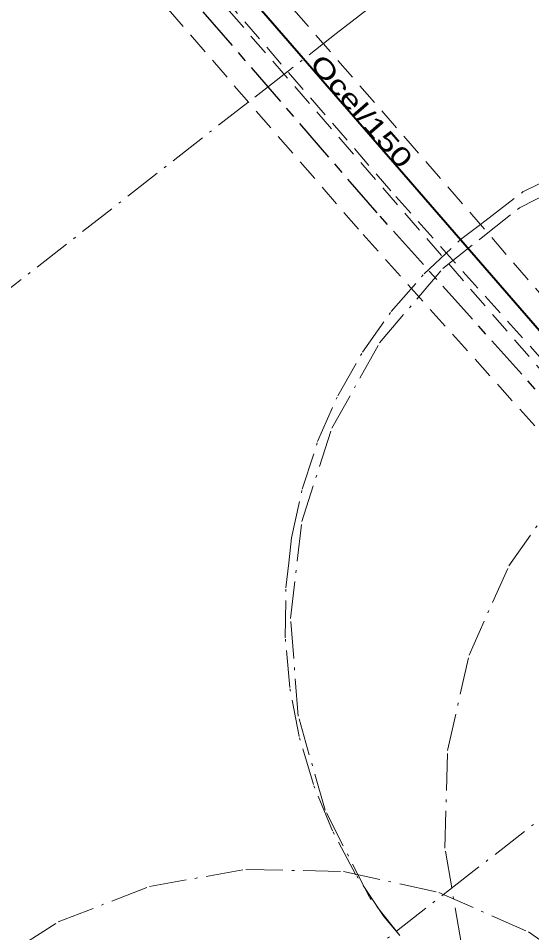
# Model space of a CAD drawing. Extents: x -588392 to -586332, y -1208963 to -1206334.
# Drawn here: x -587924.07 to -587903.38, y -1206828.1 to -1206791.27 of the extents above; entities that cross this region are included whole.
import ezdxf

# ---------------------------------------------------------------- set-up
doc = ezdxf.new("R2010")
doc.units = 0
doc.header["$LTSCALE"] = 0.3
for name, pattern in [('DOT_DASHED', [7.7, 5, -1.2, 0.3, -1.2]), ('LONG_DASH_SHORT_DASH', [9.9, 6, -1.2, 1.5, -1.2]), ('MEDIUM_DASHED', [4.5, 3, -1.5])]:
    doc.linetypes.add(name, pattern=pattern)
for name, color, linetype, lineweight in [('1', 7, 'MEDIUM_DASHED', 13), ('24', 7, 'Continuous', 25), ('51', 7, 'MEDIUM_DASHED', 13), ('55', 7, 'LONG_DASH_SHORT_DASH', 25), ('7', 7, 'MEDIUM_DASHED', 13)]:
    doc.layers.add(name, color=color, linetype=linetype, lineweight=lineweight)
doc.layers.add('30', color=7, linetype='Continuous')

msp = doc.modelspace()

# ---------------------------------------------------------------- linework, layer by layer
at = {"layer": '1'}
msp.add_lwpolyline([(-587926.025, -1206775.891), (-587925.751, -1206776.201), (-587925.351, -1206776.654), (-587897.549, -1206808.683), (-587897.277, -1206808.996), (-587897.335, -1206809.823), (-587897.648, -1206810.094), (-587897.961, -1206810.366), (-587898.788, -1206810.308), (-587899.059, -1206809.995), (-587926.857, -1206777.972), (-587927.251, -1206777.525), (-587927.525, -1206777.214), (-587927.473, -1206776.387), (-587927.163, -1206776.113), (-587926.852, -1206775.839)], close=True, dxfattribs=at)
at = {"layer": '1', "linetype": 'DOT_DASHED'}
for points in [[(-587925.141, -1206802.72), (-587914.541, -1206794.443), (-587914.182, -1206794.163), (-587911.256, -1206791.883), (-587910.616, -1206791.384), (-587902.174, -1206784.801)], [(-587908.7, -1206828.22), (-587909.343, -1206827.445), (-587910.465, -1206825.773), (-587911.415, -1206823.996), (-587912.181, -1206822.134), (-587912.755, -1206820.203), (-587913.133, -1206818.225), (-587913.311, -1206816.219), (-587913.286, -1206814.206), (-587913.172, -1206813.205), (-587913.058, -1206812.204), (-587912.632, -1206810.236), (-587912.009, -1206808.321), (-587911.197, -1206806.477), (-587910.204, -1206804.725), (-587909.041, -1206803.081), (-587907.718, -1206801.563), (-587906.249, -1206800.185), (-587905.449, -1206799.573), (-587905.279, -1206799.443), (-587903.714, -1206798.246), (-587900.178, -1206796.51)], [(-587908.696, -1206828.217), (-587909.918, -1206826.672), (-587911.712, -1206823.165), (-587912.788, -1206819.375), (-587913.104, -1206815.448), (-587912.647, -1206811.535), (-587911.435, -1206807.786), (-587909.516, -1206804.346), (-587906.962, -1206801.346), (-587905.417, -1206800.124), (-587903.872, -1206798.902), (-587900.365, -1206797.108)], [(-587906.215, -1206828.582), (-587906.881, -1206824.698), (-587906.775, -1206820.76), (-587905.904, -1206816.918), (-587904.3, -1206813.319), (-587902.025, -1206810.103), (-587900.595, -1206808.748), (-587899.165, -1206807.393), (-587895.832, -1206805.292), (-587892.154, -1206803.883), (-587888.27, -1206803.217), (-587884.332, -1206803.323), (-587880.49, -1206804.194), (-587876.891, -1206805.798), (-587873.675, -1206808.073), (-587872.32, -1206809.503), (-587872.156, -1206809.676), (-587870.801, -1206811.106), (-587868.7, -1206814.439), (-587867.291, -1206818.117), (-587866.625, -1206822.001), (-587866.731, -1206825.939), (-587867.602, -1206829.781)], [(-587980.539, -1206914.219), (-587943.819, -1206854.247), (-587929.75, -1206834.129), (-587928.621, -1206832.515), (-587925.777, -1206829.788), (-587922.456, -1206827.669), (-587918.785, -1206826.239), (-587914.906, -1206825.553), (-587910.967, -1206825.636), (-587907.12, -1206826.487), (-587903.513, -1206828.071), (-587901.899, -1206829.2), (-587900.285, -1206830.329), (-587897.558, -1206833.173), (-587895.439, -1206836.494), (-587894.009, -1206840.165), (-587893.323, -1206844.044), (-587893.406, -1206847.983), (-587894.257, -1206851.83), (-587895.841, -1206855.437), (-587896.97, -1206857.051), (-587910.341, -1206876.173), (-587946.581, -1206935.361)]]:
    msp.add_lwpolyline(points, dxfattribs=at)
at = {"layer": '24', "lineweight": 40}
msp.add_lwpolyline([(-587926.501, -1206776.863), (-587926.104, -1206777.313), (-587898.304, -1206809.339)], dxfattribs=at)
at = {"layer": '51', "linetype": 'DOT_DASHED'}
msp.add_lwpolyline([(-587912.489, -1206830.893), (-587906.69, -1206826.375), (-587896.084, -1206818.093), (-587895.738, -1206817.823), (-587892.817, -1206815.548), (-587892.171, -1206815.044), (-587883.726, -1206808.458), (-587872.95, -1206800.055), (-587829.182, -1206765.921)], dxfattribs=at)
at = {"layer": '55'}
msp.add_lwpolyline([(-587894.342, -1206810.552), (-587894.539, -1206810.692), (-587896.46, -1206812.27), (-587897.208, -1206812.884), (-587899.82, -1206810.03), (-587909.61, -1206799.11), (-587921.01, -1206785.93), (-587925.2, -1206780.79)], dxfattribs=at)
at = {"layer": '7'}
msp.add_lwpolyline([(-587920.244, -1206785.287), (-587908.859, -1206798.449), (-587899.079, -1206809.359), (-587897.11, -1206811.51), (-587897.095, -1206811.497), (-587895.147, -1206809.897), (-587894.921, -1206809.737), (-587894.583, -1206809.497), (-587893.767, -1206809.635), (-587893.527, -1206809.973), (-587893.287, -1206810.311), (-587893.425, -1206811.127), (-587893.763, -1206811.367), (-587893.931, -1206811.487), (-587895.825, -1206813.043), (-587896.574, -1206813.657), (-587896.882, -1206813.91), (-587897.677, -1206813.853), (-587897.946, -1206813.559), (-587900.561, -1206810.701), (-587910.361, -1206799.771), (-587921.776, -1206786.573)], dxfattribs=at)

# ---------------------------------------------------------------- texts
at = {"layer": '30', "width": 1.4}
msp.add_text('Ocel/150', height=0.75, rotation=310.959, dxfattribs=at).set_placement((-587912.368, -1206793.137))

doc.saveas('drawing.dxf')
